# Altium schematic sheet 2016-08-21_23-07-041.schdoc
size 441 x 220 mm; SheetNumber: 1; SheetTotal: 1
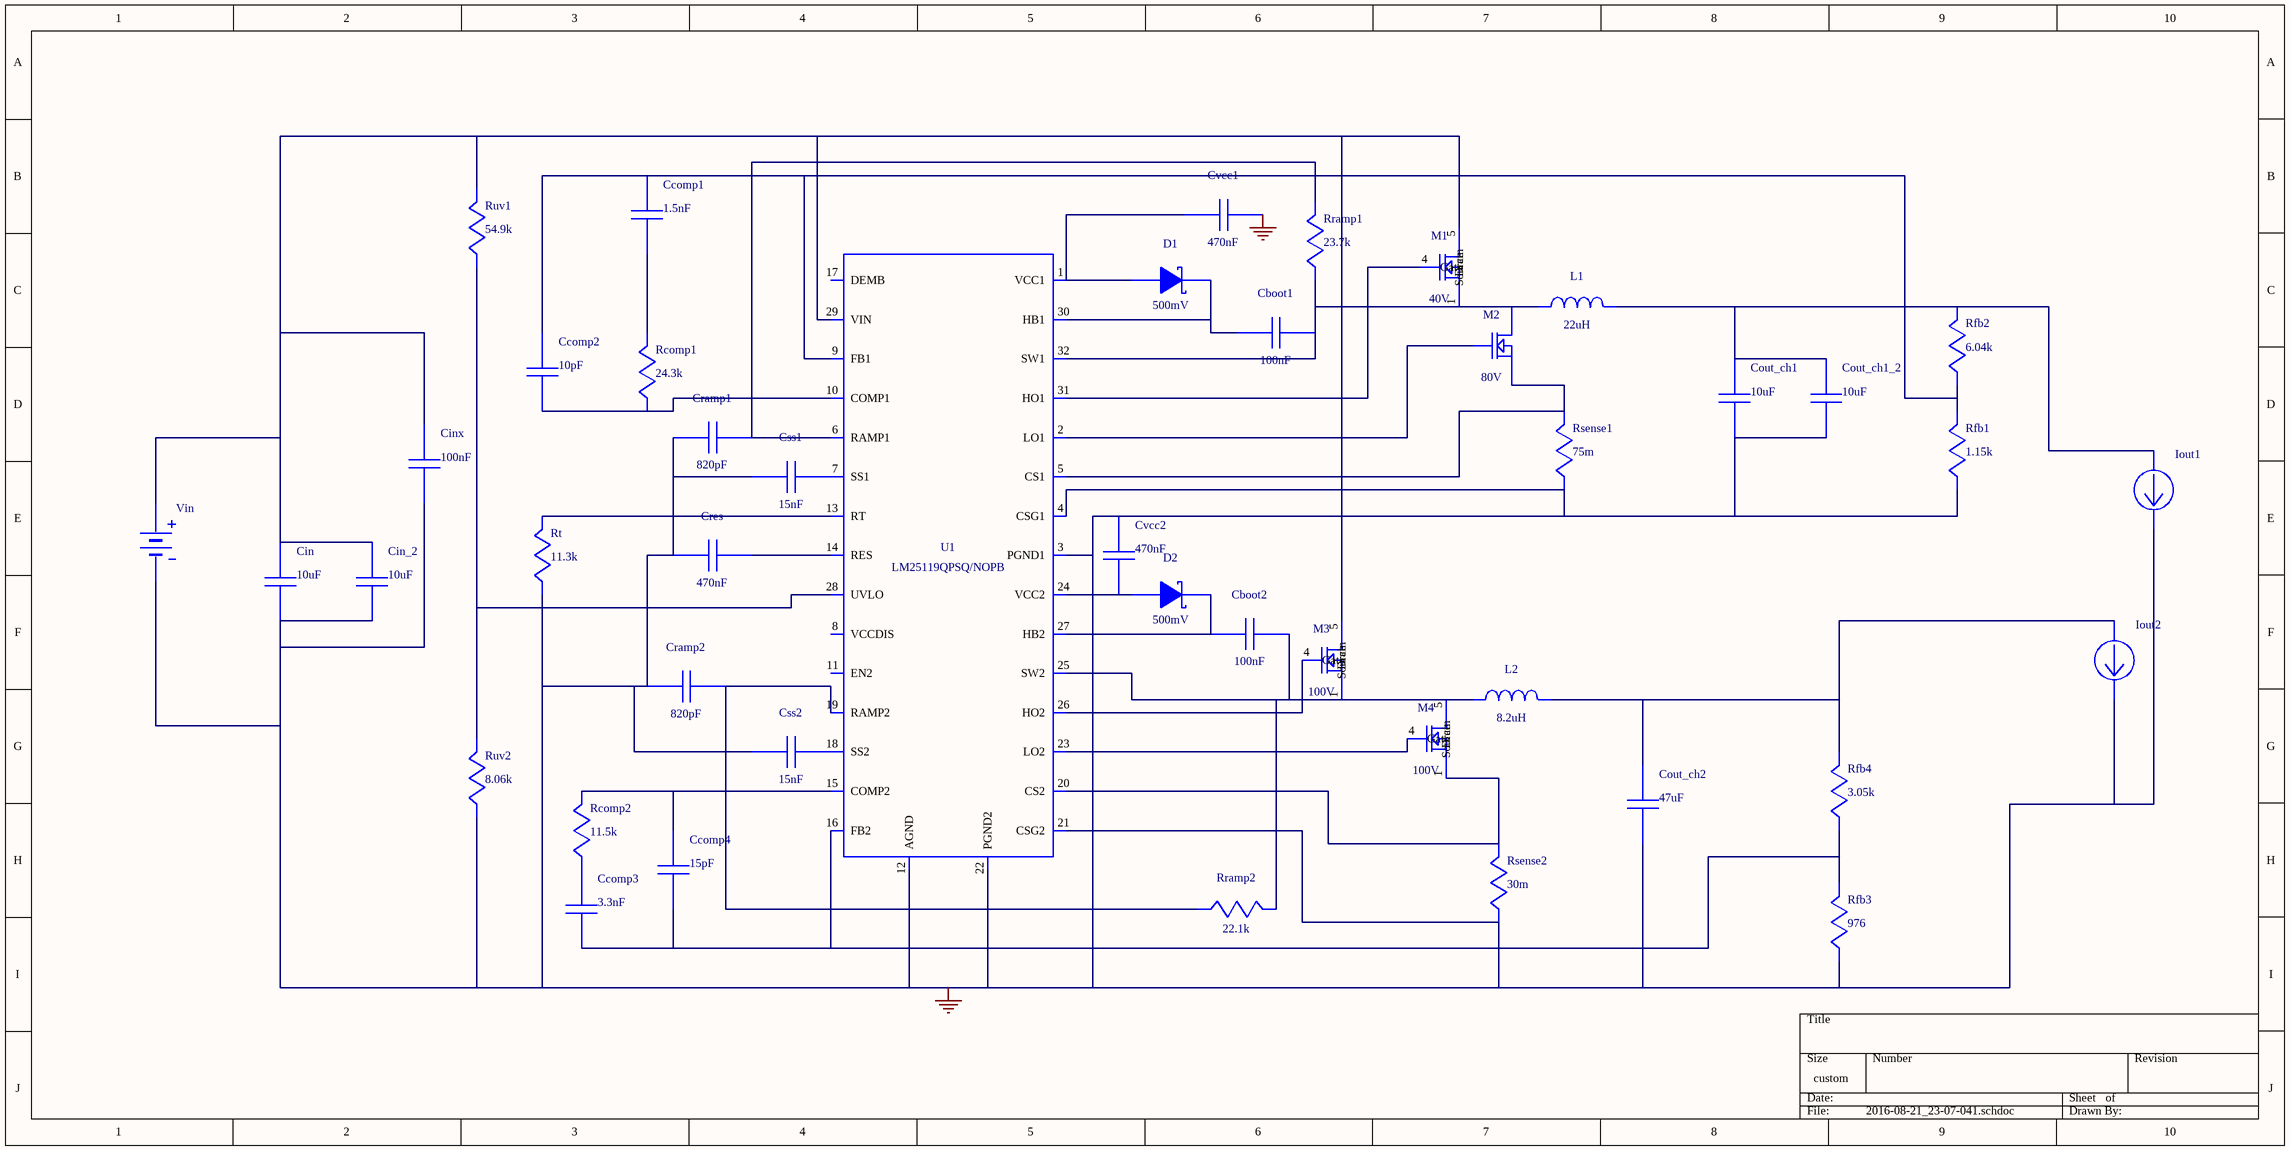
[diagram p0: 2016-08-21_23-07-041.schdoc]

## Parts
Cboot1  value 100nF  (hidden comment: GRM155R61A104KA01D)
Cboot2  value 100nF  (hidden comment: GRM155R61A104KA01D)
Ccomp1  value 1.5nF  (hidden comment: CC0805KRX7R9BB152)
Ccomp2  value 10pF  (hidden comment: C0805C100K5GACTU)
Ccomp3  value 3.3nF  (hidden comment: GRM216R71E332KA01D)
Ccomp4  value 15pF  (hidden comment: CC0805JRNPO9BN150)
Cin  value 10uF  (hidden comment: GRM32ER7YA106KA12L)
Cin_2  value 10uF  (hidden comment: GRM32ER7YA106KA12L)
Cinx  value 100nF  (hidden comment: C0805C104K5RACTU)
Cout_ch1  value 10uF  (hidden comment: GRM188R60J106ME47D)
Cout_ch1_2  value 10uF  (hidden comment: GRM188R60J106ME47D)
Cout_ch2  value 47uF  (hidden comment: GRM31CC80J476KE18L)
Cramp1  value 820pF  (hidden comment: CC0805KRX7R9BB821)
Cramp2  value 820pF  (hidden comment: CC0805KRX7R9BB821)
Cres  value 470nF  (hidden comment: GRM155C80J474KE19D)
Css1  value 15nF  (hidden comment: CC0805KRX7R9BB153)
Css2  value 15nF  (hidden comment: CC0805KRX7R9BB153)
Cvcc1  value 470nF  (hidden comment: GRM155R61A474KE15D)
Cvcc2  value 470nF  (hidden comment: GRM155R61A474KE15D)
D1  value 500mV  (hidden comment: SS14-E3/61T)
D2  value 500mV  (hidden comment: SS14-E3/61T)
Iout1  WB_CURRENT_LOAD  (value not drawn)
Iout2  WB_CURRENT_LOAD  (value not drawn)
L1  value 22uH  (hidden comment: SRN6045-220M)
L2  value 8.2uH  (hidden comment: SRN8040-8R2Y)
M1  value 40V  (hidden comment: CSD18504Q5A)
M2  value 80V  (hidden comment: BSC340N08NS3 G)
M3  value 100V  (hidden comment: CSD19537Q3)
M4  value 100V  (hidden comment: CSD19537Q3)
Rcomp1  value 24.3k  (hidden comment: CRCW040224K3FKED)
Rcomp2  value 11.5k  (hidden comment: CRCW040211K5FKED)
Rfb1  value 1.15k  (hidden comment: CRCW04021K15FKED)
Rfb2  value 6.04k  (hidden comment: CRCW04026K04FKED)
Rfb3  value 976  (hidden comment: CRCW0402976RFKED)
Rfb4  value 3.05k  (hidden comment: RT0805BRD073K05L)
Rramp1  value 23.7k  (hidden comment: CRCW040223K7FKED)
Rramp2  value 22.1k  (hidden comment: CRCW040222K1FKED)
Rsense1  value 75m  (hidden comment: ERJ-L03UF75MV)
Rsense2  value 30m  (hidden comment: CSR1206FK30L0)
Rt  value 11.3k  (hidden comment: CRCW040211K3FKED)
Ruv1  value 54.9k  (hidden comment: CRCW040254K9FKED)
Ruv2  value 8.06k  (hidden comment: CRCW04028K06FKED)
U1  LM5119PSQ/NOPB  (value not drawn)
Vin  WB_BATTERY  (value not drawn)

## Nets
0: Cin.2 Cin_2.2 Cinx.2 Cout_ch1.2 Cout_ch1_2.2 Cout_ch2.2 Cramp1.2 Cramp2.2 Cres.2 Css1.2 Css2.2 Cvcc1.2 Cvcc2.2 Iout1.2(-) Iout2.2(-) Rfb1.2 Rfb3.2 Rsense1.2 Rsense2.2 Rt.2 Ruv2.2 U1.3(PGND1) U1.4(CSG1) U1.12(AGND) U1.21(CSG2) U1.22(PGND2) U1.33(EP) Vin.2(-)
NetCboot1_1: Cboot1.1 L1.1 M1.1(Source) M1.2(Source) M1.3(Source) M2.5(Drain) M2.6(Drain) M2.7(Drain) M2.8(Drain) M2.9(Drain) Rramp1.2 U1.32(SW1)
NetCboot1_2: Cboot1.2 D1.1(K) U1.30(HB1)
NetCboot2_1: Cboot2.1 L2.1 M3.1(Source) M3.2(Source) M3.3(Source) M4.5(Drain) M4.6(Drain) M4.7(Drain) M4.8(Drain) M4.9(Drain) Rramp2.1 U1.25(SW2)
NetCboot2_2: Cboot2.2 D2.1(K) U1.27(HB2)
NetCcomp1_1: Ccomp1.1 Rcomp1.1
NetCcomp1_2: Ccomp1.2 Ccomp2.2 Rfb1.1 Rfb2.2 U1.9(FB1)
NetCcomp2_1: Ccomp2.1 Rcomp1.2 U1.10(COMP1)
NetCcomp3_1: Ccomp3.1 Rcomp2.2
NetCcomp3_2: Ccomp3.2 Ccomp4.2 Rfb3.1 Rfb4.2 U1.16(FB2)
NetCcomp4_1: Ccomp4.1 Rcomp2.1 U1.15(COMP2)
NetCin_1: Cin.1 Cin_2.1 Cinx.1 M1.5(Drain) M1.6(Drain) M1.7(Drain) M1.8(Drain) M1.9(Drain) M3.5(Drain) M3.6(Drain) M3.7(Drain) M3.8(Drain) M3.9(Drain) Ruv1.1 U1.29(VIN) Vin.1(+)
NetCout_ch1_1: Cout_ch1.1 Cout_ch1_2.1 Iout1.1(+) L1.2 Rfb2.1
NetCout_ch2_1: Cout_ch2.1 Iout2.1(+) L2.2 Rfb4.1
NetCramp1_1: Cramp1.1 Rramp1.1 U1.6(RAMP1)
NetCramp2_1: Cramp2.1 Rramp2.2 U1.19(RAMP2)
NetCres_1: Cres.1 U1.14(RES)
NetCss1_1: Css1.1 U1.7(SS1)
NetCss2_1: Css2.1 U1.18(SS2)
NetCvcc1_1: Cvcc1.1 D1.2(A) U1.1(VCC1)
NetCvcc2_1: Cvcc2.1 D2.2(A) U1.24(VCC2)
NetM1_4: M1.4(Gate) U1.31(HO1)
NetM2_1: M2.1(Source) M2.2(Source) M2.3(Source) Rsense1.1 U1.5(CS1)
NetM2_4: M2.4(Gate) U1.2(LO1)
NetM3_4: M3.4(Gate) U1.26(HO2)
NetM4_1: M4.1(Source) M4.2(Source) M4.3(Source) Rsense2.1 U1.20(CS2)
NetM4_4: M4.4(Gate) U1.23(LO2)
NetRt_1: Rt.1 U1.13(RT)
NetRuv1_2: Ruv1.2 Ruv2.1 U1.28(UVLO)

Not connected (* = marked no-connect by the designer): U1 8(VCCDIS) 11(EN2) 17(DEMB)

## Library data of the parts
Cboot1 Cboot2 = GRM155R61A104KA01D: GRM155R61A104KA0; Manufacturer Name: MuRata
Ccomp1 = CC0805KRX7R9BB152: CC0805KRX7R9BB15; Manufacturer Name: Yageo America
Ccomp2 = C0805C100K5GACTU: Manufacturer Name: Kemet
Ccomp3 = GRM216R71E332KA01D: GRM216R71E332KA0; Manufacturer Name: MuRata
Ccomp4 = CC0805JRNPO9BN150: CC0805JRNPO9BN15; Manufacturer Name: Yageo America
Cin Cin_2 = GRM32ER7YA106KA12L: GRM32ER7YA106KA1; Manufacturer Name: MuRata
Cinx = C0805C104K5RACTU: Manufacturer Name: Kemet
Cout_ch1 Cout_ch1_2 = GRM188R60J106ME47D: GRM188R60J106ME4; Manufacturer Name: MuRata
Cout_ch2 = GRM31CC80J476KE18L: GRM31CC80J476KE1; Manufacturer Name: MuRata
Cramp1 Cramp2 = CC0805KRX7R9BB821: CC0805KRX7R9BB82; Manufacturer Name: Yageo America
Cres = GRM155C80J474KE19D: GRM155C80J474KE1; Manufacturer Name: MuRata
Css1 Css2 = CC0805KRX7R9BB153: CC0805KRX7R9BB00; Manufacturer Name: Yageo America
Cvcc1 Cvcc2 = GRM155R61A474KE15D: GRM155R61A474KE1; Manufacturer Name: MuRata
D1 D2 = SS14-E3/61T: Manufacturer Name: Vishay-Semiconductor
L1 = SRN6045-220M: Manufacturer Name: Bourns
L2 = SRN8040-8R2Y: Manufacturer Name: Bourns
M1 = CSD18504Q5A: Manufacturer Name: Texas Instruments
M2 = BSC340N08NS3 G: Manufacturer Name: Infineon Technologies
M3 M4 = CSD19537Q3: Manufacturer Name: Texas Instruments
Rcomp1 = CRCW040224K3FKED: Manufacturer Name: Vishay-Dale
Rcomp2 = CRCW040211K5FKED: Manufacturer Name: Vishay-Dale
Rfb1 = CRCW04021K15FKED: Manufacturer Name: Vishay-Dale
Rfb2 = CRCW04026K04FKED: Manufacturer Name: Vishay-Dale
Rfb3 = CRCW0402976RFKED: Manufacturer Name: Vishay-Dale
Rfb4 = RT0805BRD073K05L: Manufacturer Name: Yageo America
Rramp1 = CRCW040223K7FKED: Manufacturer Name: Vishay-Dale
Rramp2 = CRCW040222K1FKED: Manufacturer Name: Vishay-Dale
Rsense1 = ERJ-L03UF75MV: Manufacturer Name: Panasonic
Rsense2 = CSR1206FK30L0: Manufacturer Name: Stackpole Electronics Inc
Rt = CRCW040211K3FKED: Manufacturer Name: Vishay-Dale
Ruv1 = CRCW040254K9FKED: Manufacturer Name: Vishay-Dale
Ruv2 = CRCW04028K06FKED: Manufacturer Name: Vishay-Dale
U1 = LM5119PSQ/NOPB: LM25119QPSQ/NOPB; Manufacturer Name: Texas Instruments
